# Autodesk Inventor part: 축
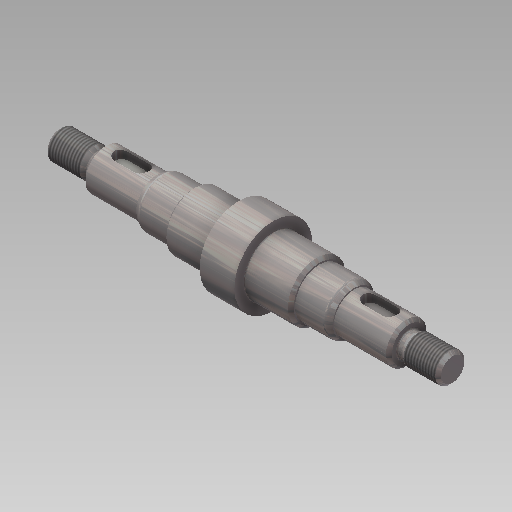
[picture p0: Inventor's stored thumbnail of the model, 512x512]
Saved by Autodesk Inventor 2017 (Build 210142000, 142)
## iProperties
Created: 2019-09
Part Number: 축
Material: 강철, 연강
Document SubType Name: Modeling
Designer: mduedu
Density: 7.86 g/cm^3
Mass: 210.278 g
Surface Area: 69.4769 cm^2
Volume: 26.7529 cm^3
Appearance: 강철
Author: mduedu
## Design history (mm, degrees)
sketch "스케치1"
  geometry: L1 (0, 0)-(15, 0); L2 (15, 0)-(15, 5); L3 (15, 5)-(0, 5); L4 (0, 5)-(0, 0); L5 (15, 0)-(34, 0); L6 (34, 0)-(34, 7); L7 (34, 7)-(15, 7); L8 (15, 7)-(15, 0); L9 (34, 0)-(46, 0); L10 (46, 0)-(46, 8.5); L11 (46, 8.5)-(34, 8.5); L12 (34, 8.5)-(34, 0); L13 (46, 0)-(62, 0); L14 (62, 10)-(46, 10); L15 (46, 10)-(46, 0); L16 (62, 10)-(62, 0); L17 (62, 0)-(68, 0); L18 (68, 0)-(68, 13.5); L19 (68, 13.5)-(62, 13.5); L20 (62, 13.5)-(62, 0)
  constraints: 40 end point, 10 parallel, 5 horizontal, 4 perpendicular, 1 vertical
  dimensions: "d2" = 15 distance of L2.end L3.end; "d3" = 19 distance of L6.end L7.end; "d8" = 16 distance of L14.start L14.end; "d9" = 10 diameter of L3 L1; "d10" = 14 diameter of L7 L5; "d11" = 17 diameter of L11 L9; "d12" = 20 diameter of L14 L13; "d73" = 12 distance of L10.end L11.end (derived); "d74" = 27 diameter of L19 L17; "d75" = 6 distance of L18.end L19.end; "d76" = 68 distance between parallel lines of L4 L18
revolve "회전1" sketch "스케치1" stored, may be unused: angle "d17" = 90 deg
revolve "회전2" stored, may be unused: angle "d22" = 90 deg
fillet "모깎기1" dims "d23" = 0.6
feature "스레드1" dims "d24" = 10, "d25" = 0
chamfer "모따기1" distance "d26" = 1; stored, may be unused: second distance "d27" = 2, angle "d28" = 45 deg
chamfer "모따기2" distance "d29" = 1; stored, may be unused: second distance "d30" = 2, angle "d31" = 45 deg
chamfer "모따기3" distance "d32" = 1.819; stored, may be unused: second distance "d33" = 2, angle "d34" = 30 deg
fillet "모깎기2" dims "d35" = 2
chamfer "모따기4" distance "d36" = 1; stored, may be unused: second distance "d37" = 2, angle "d38" = 30 deg
fillet "모깎기3" dims "d39" = 0.3
node "작업 평면1"
sketch "스케치3" dims "d51" = 12
  geometry: L1 (3, -2.5)-(-4, -2.5); L2 (-4, -2.5)-(-4, 2.5); L3 (-4, 2.5)-(3, 2.5); L4 (3, 2.5)-(3, -2.5); L5 (-9.5, 7.45)-(-9.5, -7.45) reference; 3 further points
  constraints: 8 end point, 2 midpoint, 2 parallel, 2 vertical alignment, 1 horizontal, 1 horizontal alignment, 1 perpendicular, 4 other
  dimensions: "d50" = 3 dimension on L5; "d52" = 5 distance between parallel lines of L3 L1
extrude "돌출1" cut sketch "스케치3" distance "d53" = 3; taper "d54" = 0 deg
node "솔리드1"
mirror "대칭1"
sketch "스케치2"
  geometry: L1 (0, -5)-(0, 5) reference; L2 (0, 5)-(15, 5) reference; L3 (15, 5)-(15, 7) reference; L4 (15, 7)-(34, 7) reference; L5 (34, 7)-(34, 8.5) reference; L6 (34, 8.5)-(46, 8.5) reference; L7 (46, 8.5)-(46, 10) reference; L8 (46, 10)-(62, 10) reference; L9 (62, -10)-(46, -10) reference; L10 (46, -10)-(46, -8.5) reference; L11 (46, -8.5)-(34, -8.5) reference; L12 (34, -8.5)-(34, -7) reference; L13 (34, -7)-(15, -7) reference; L14 (15, -7)-(15, -5) reference; L15 (15, -5)-(0, -5) reference; L16 (0, 0)-(74, 0); L17 (15, 5)-(12.014, 5); L18 (13.4, 4.2)-(15, 4.2); L19 (15, 4.2)-(15, 5); L20 (12.014, 5)-(13.4, 4.2); L21 (62, 10)-(62, 13.5) reference; L22 (62, 13.5)-(68, 13.5) reference; L23 (68, 13.5)-(68, -13.5) reference; L24 (68, -13.5)-(62, -13.5) reference; L25 (62, -13.5)-(62, -10) reference
  constraints: 10 end point, 1 horizontal, 1 parallel, 1 vertical
  dimensions: "d18" = 30 deg angle of L2 L20; "d19" = 8.4 diameter of L18 L16; "d21" = 2.986 distance from line of L17.end L19
node "절단 모서리 투영1"
